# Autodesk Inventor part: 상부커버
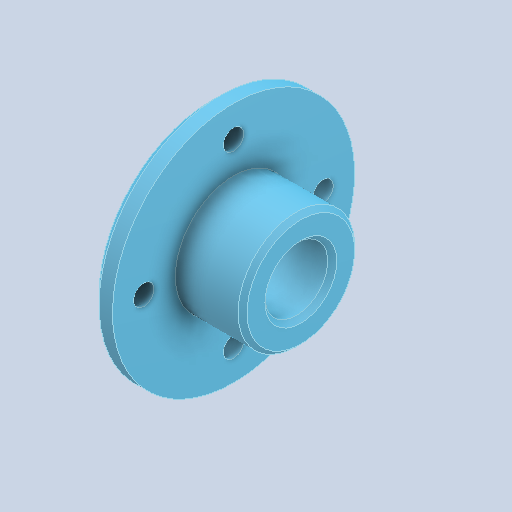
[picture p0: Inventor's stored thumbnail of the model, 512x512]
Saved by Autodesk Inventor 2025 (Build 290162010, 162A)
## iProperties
Created: 2024-07
Part Number: 상부커버
Material: 알루미늄 6061
Document SubType Name: Modeling
Designer: Admin
Density: 2.71 g/cm^3
Appearance: 기본값
Author: jhkim
Sending System: Autodesk Inventor 2025
Preprocessor: ST-DEVELOPER v20
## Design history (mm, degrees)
feature "솔리드1"
node "솔리드2"
